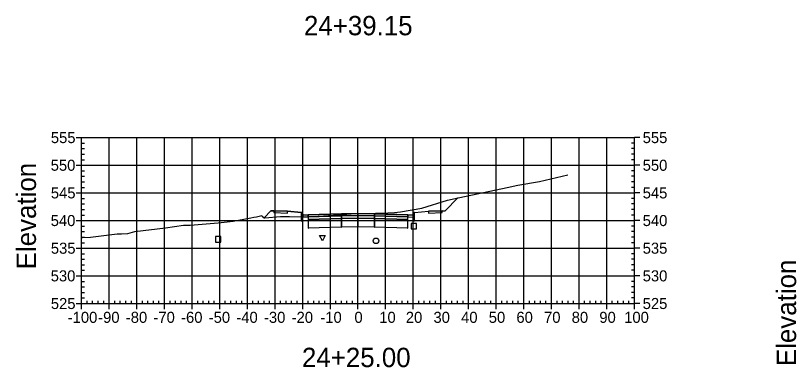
# Model space of a CAD drawing. Extents: x 704834 to 709892, y 372981 to 377533.
# Drawn here: x 707731 to 708013.5, y 376927.7 to 377054.9 of the extents above; entities that cross this region are included whole.
import ezdxf

# ---------------------------------------------------------------- set-up
doc = ezdxf.new("R2010")
doc.units = 0
for name, color, linetype in [('1', 7, 'Continuous'), ('10', 7, 'Continuous'), ('13', 7, 'Continuous'), ('14', 7, 'Continuous'), ('4', 7, 'Continuous'), ('57', 7, 'Continuous'), ('60', 7, 'Continuous'), ('Default_Xsect', 7, 'Continuous'), ('Existing', 7, 'Continuous')]:
    doc.layers.add(name, color=color, linetype=linetype)

msp = doc.modelspace()

# ---------------------------------------------------------------- linework, layer by layer
for points in [[(707886.41, 376984.32), (707891.09, 376988.99)], [(707823.41, 376984.32), (707820.92, 376981.82)], [(707824.41, 376984.36), (707823.41, 376984.32)], [(707885.41, 376984.36), (707886.41, 376984.32)], [(707834.41, 376983.76), (707829.41, 376984.16)], [(707875.41, 376983.76), (707880.41, 376984.16)]]:
    msp.add_lwpolyline(points)
for points in [[(707829.41, 376984.16), (707824.41, 376984.36), (707824.41, 376983.69), (707829.41, 376983.49)], [(707880.41, 376983.49), (707885.41, 376983.69), (707885.41, 376984.36), (707880.41, 376984.16)], [(707834.91, 376982.76), (707834.83, 376983.76), (707834.41, 376983.76), (707834.41, 376980.76), (707834.91, 376980.76)], [(707836.91, 376982.84), (707834.91, 376982.76), (707834.91, 376982.09), (707836.91, 376982.17)], [(707848.91, 376983.2), (707836.91, 376982.84), (707836.91, 376982.17), (707848.91, 376982.53)], [(707848.91, 376982.53), (707836.91, 376982.17), (707836.91, 376981.17), (707848.91, 376981.53)], [(707848.91, 376981.53), (707836.91, 376981.17), (707836.91, 376978.17), (707848.91, 376978.53)], [(707848.86, 376982.48), (707848.96, 376982.48), (707848.96, 376982.58), (707848.86, 376982.58)], [(707848.86, 376981.48), (707848.96, 376981.48), (707848.96, 376981.58), (707848.86, 376981.58)], [(707854.91, 376983.32), (707848.91, 376983.2), (707848.91, 376982.53), (707854.91, 376982.65)], [(707854.91, 376982.65), (707848.91, 376982.53), (707848.91, 376981.53), (707854.91, 376981.65)], [(707854.91, 376981.65), (707848.91, 376981.53), (707848.91, 376978.53), (707854.91, 376978.65)], [(707854.86, 376982.6), (707854.96, 376982.6), (707854.96, 376982.7), (707854.86, 376982.7)], [(707854.86, 376981.6), (707854.96, 376981.6), (707854.96, 376981.7), (707854.86, 376981.7)], [(707854.91, 376982.65), (707860.91, 376982.53), (707860.91, 376983.2), (707854.91, 376983.32)], [(707854.91, 376981.65), (707860.91, 376981.53), (707860.91, 376982.53), (707854.91, 376982.65)], [(707854.91, 376978.65), (707860.91, 376978.53), (707860.91, 376981.53), (707854.91, 376981.65)], [(707860.86, 376982.48), (707860.96, 376982.48), (707860.96, 376982.58), (707860.86, 376982.58)], [(707860.86, 376981.48), (707860.96, 376981.48), (707860.96, 376981.58), (707860.86, 376981.58)], [(707860.91, 376982.53), (707872.91, 376982.17), (707872.91, 376982.84), (707860.91, 376983.2)], [(707860.91, 376981.53), (707872.91, 376981.17), (707872.91, 376982.17), (707860.91, 376982.53)], [(707860.91, 376978.53), (707872.91, 376978.17), (707872.91, 376981.17), (707860.91, 376981.53)], [(707872.91, 376982.17), (707874.91, 376982.09), (707874.91, 376982.76), (707872.91, 376982.84)], [(707874.91, 376980.76), (707875.41, 376980.76), (707875.41, 376983.76), (707875, 376983.76), (707874.91, 376982.76)], [(707836.86, 376981.12), (707836.96, 376981.12), (707836.96, 376981.22), (707836.86, 376981.22)], [(707854.86, 376978.6), (707854.96, 376978.6), (707854.96, 376978.7), (707854.86, 376978.7)], [(707872.86, 376981.12), (707872.96, 376981.12), (707872.96, 376981.22), (707872.86, 376981.22)], [(707836.86, 376978.12), (707836.96, 376978.12), (707836.96, 376978.22), (707836.86, 376978.22)], [(707848.86, 376978.48), (707848.96, 376978.48), (707848.96, 376978.58), (707848.86, 376978.58)], [(707860.86, 376978.48), (707860.96, 376978.48), (707860.96, 376978.58), (707860.86, 376978.58)], [(707872.86, 376978.12), (707872.96, 376978.12), (707872.96, 376978.22), (707872.86, 376978.22)]]:
    msp.add_lwpolyline(points, close=True)
at = {"layer": '1'}
msp.add_lwpolyline([(707842.01, 376973.47), (707841.01, 376975.47), (707843.01, 376975.47)], close=True, dxfattribs=at)
at = {"layer": '10'}
msp.add_lwpolyline([(707803.33, 376973.05), (707805.33, 376973.05), (707805.33, 376975.05), (707803.33, 376975.05)], close=True, dxfattribs=at)
at = {"layer": '13'}
msp.add_circle((707861.43, 376973.48), 1, dxfattribs=at)
at = {"layer": '14'}
for points in [[(707891.09, 376988.99), (707891.09, 376989.04), (707891.09, 376988.99), (707891.04, 376988.99), (707891.09, 376988.99), (707891.09, 376988.94), (707891.09, 376988.99), (707891.14, 376988.99)], [(707820.92, 376981.82), (707820.92, 376981.87), (707820.92, 376981.82), (707820.87, 376981.82), (707820.92, 376981.82), (707820.92, 376981.77), (707820.92, 376981.82), (707820.97, 376981.82)], [(707836.91, 376982.84), (707836.91, 376982.89), (707836.91, 376982.84), (707836.86, 376982.84), (707836.91, 376982.84), (707836.91, 376982.79), (707836.91, 376982.84), (707836.96, 376982.84)], [(707854.91, 376983.32), (707854.91, 376983.37), (707854.91, 376983.32), (707854.86, 376983.32), (707854.91, 376983.32), (707854.91, 376983.27), (707854.91, 376983.32), (707854.96, 376983.32)], [(707872.91, 376982.84), (707872.91, 376982.89), (707872.91, 376982.84), (707872.86, 376982.84), (707872.91, 376982.84), (707872.91, 376982.79), (707872.91, 376982.84), (707872.96, 376982.84)]]:
    msp.add_lwpolyline(points, dxfattribs=at)
at = {"layer": '4'}
msp.add_lwpolyline([(707874.12, 376977.8), (707876.12, 376977.8), (707876.12, 376979.8), (707874.12, 376979.8)], close=True, dxfattribs=at)
at = {"layer": '57'}
for p, q in [((707752.91, 377010.82), (707754.91, 377010.82)), ((707754.91, 377010.82), (707954.91, 377010.82)), ((707754.91, 376950.82), (707754.91, 377010.82)), ((707754.91, 376950.82), (707754.91, 377010.82)), ((707764.91, 376950.82), (707764.91, 377010.82)), ((707774.91, 376950.82), (707774.91, 377010.82)), ((707784.91, 376950.82), (707784.91, 377010.82)), ((707794.91, 376950.82), (707794.91, 377010.82)), ((707804.91, 376950.82), (707804.91, 377010.82)), ((707814.91, 376950.82), (707814.91, 377010.82)), ((707824.91, 376950.82), (707824.91, 377010.82)), ((707834.91, 376950.82), (707834.91, 377010.82)), ((707844.91, 376950.82), (707844.91, 377010.82)), ((707854.91, 376950.82), (707854.91, 377010.82)), ((707864.91, 376950.82), (707864.91, 377010.82)), ((707874.91, 376950.82), (707874.91, 377010.82)), ((707884.91, 376950.82), (707884.91, 377010.82)), ((707894.91, 376950.82), (707894.91, 377010.82)), ((707904.91, 376950.82), (707904.91, 377010.82)), ((707914.91, 376950.82), (707914.91, 377010.82)), ((707924.91, 376950.82), (707924.91, 377010.82)), ((707934.91, 376950.82), (707934.91, 377010.82)), ((707944.91, 376950.82), (707944.91, 377010.82)), ((707954.91, 376950.82), (707954.91, 377010.82)), ((707954.91, 376950.82), (707954.91, 377010.82)), ((707956.91, 377010.82), (707954.91, 377010.82)), ((707754.91, 377008.82), (707755.91, 377008.82)), ((707954.91, 377008.82), (707953.91, 377008.82)), ((707754.91, 377006.82), (707755.91, 377006.82)), ((707754.91, 377004.82), (707755.91, 377004.82)), ((707954.91, 377006.82), (707953.91, 377006.82)), ((707954.91, 377004.82), (707953.91, 377004.82)), ((707754.91, 377002.82), (707755.91, 377002.82)), ((707954.91, 377002.82), (707953.91, 377002.82)), ((707752.91, 377000.82), (707754.91, 377000.82)), ((707754.91, 377000.82), (707954.91, 377000.82)), ((707754.91, 376998.82), (707755.91, 376998.82)), ((707954.91, 376998.82), (707953.91, 376998.82)), ((707956.91, 377000.82), (707954.91, 377000.82)), ((707754.91, 376996.82), (707755.91, 376996.82)), ((707954.91, 376996.82), (707953.91, 376996.82)), ((707754.91, 376994.82), (707755.91, 376994.82)), ((707754.91, 376992.82), (707755.91, 376992.82)), ((707954.91, 376994.82), (707953.91, 376994.82)), ((707954.91, 376992.82), (707953.91, 376992.82)), ((707752.91, 376990.82), (707754.91, 376990.82)), ((707754.91, 376990.82), (707954.91, 376990.82)), ((707956.91, 376990.82), (707954.91, 376990.82)), ((707754.91, 376988.82), (707755.91, 376988.82)), ((707954.91, 376988.82), (707953.91, 376988.82)), ((707754.91, 376986.82), (707755.91, 376986.82)), ((707754.91, 376984.82), (707755.91, 376984.82)), ((707954.91, 376986.82), (707953.91, 376986.82)), ((707954.91, 376984.82), (707953.91, 376984.82)), ((707754.91, 376982.82), (707755.91, 376982.82)), ((707954.91, 376982.82), (707953.91, 376982.82)), ((707752.91, 376980.82), (707754.91, 376980.82)), ((707754.91, 376980.82), (707954.91, 376980.82)), ((707754.91, 376978.82), (707755.91, 376978.82)), ((707954.91, 376978.82), (707953.91, 376978.82)), ((707956.91, 376980.82), (707954.91, 376980.82)), ((707754.91, 376976.82), (707755.91, 376976.82)), ((707954.91, 376976.82), (707953.91, 376976.82)), ((707754.91, 376974.82), (707755.91, 376974.82)), ((707954.91, 376974.82), (707953.91, 376974.82)), ((707752.91, 376970.82), (707754.91, 376970.82)), ((707754.91, 376972.82), (707755.91, 376972.82)), ((707754.91, 376970.82), (707954.91, 376970.82)), ((707954.91, 376972.82), (707953.91, 376972.82)), ((707956.91, 376970.82), (707954.91, 376970.82)), ((707754.91, 376968.82), (707755.91, 376968.82)), ((707954.91, 376968.82), (707953.91, 376968.82)), ((707754.91, 376966.82), (707755.91, 376966.82)), ((707754.91, 376964.82), (707755.91, 376964.82)), ((707954.91, 376966.82), (707953.91, 376966.82)), ((707954.91, 376964.82), (707953.91, 376964.82)), ((707754.91, 376962.82), (707755.91, 376962.82)), ((707954.91, 376962.82), (707953.91, 376962.82)), ((707752.91, 376960.82), (707754.91, 376960.82)), ((707754.91, 376960.82), (707954.91, 376960.82)), ((707956.91, 376960.82), (707954.91, 376960.82)), ((707754.91, 376958.82), (707755.91, 376958.82)), ((707754.91, 376956.82), (707755.91, 376956.82)), ((707954.91, 376958.82), (707953.91, 376958.82)), ((707954.91, 376956.82), (707953.91, 376956.82)), ((707754.91, 376954.82), (707755.91, 376954.82)), ((707954.91, 376954.82), (707953.91, 376954.82)), ((707752.91, 376950.82), (707754.91, 376950.82)), ((707754.91, 376952.82), (707755.91, 376952.82)), ((707754.91, 376950.82), (707954.91, 376950.82)), ((707754.91, 376950.82), (707954.91, 376950.82)), ((707754.91, 376948.82), (707754.91, 376950.82)), ((707756.91, 376950.82), (707756.91, 376951.82)), ((707758.91, 376950.82), (707758.91, 376951.82)), ((707760.91, 376950.82), (707760.91, 376951.82)), ((707762.91, 376950.82), (707762.91, 376951.82)), ((707764.91, 376948.82), (707764.91, 376950.82)), ((707766.91, 376950.82), (707766.91, 376951.82)), ((707768.91, 376950.82), (707768.91, 376951.82)), ((707770.91, 376950.82), (707770.91, 376951.82)), ((707772.91, 376950.82), (707772.91, 376951.82)), ((707774.91, 376948.82), (707774.91, 376950.82)), ((707776.91, 376950.82), (707776.91, 376951.82)), ((707778.91, 376950.82), (707778.91, 376951.82)), ((707780.91, 376950.82), (707780.91, 376951.82)), ((707782.91, 376950.82), (707782.91, 376951.82)), ((707784.91, 376948.82), (707784.91, 376950.82)), ((707786.91, 376950.82), (707786.91, 376951.82)), ((707788.91, 376950.82), (707788.91, 376951.82)), ((707790.91, 376950.82), (707790.91, 376951.82)), ((707792.91, 376950.82), (707792.91, 376951.82)), ((707794.91, 376948.82), (707794.91, 376950.82)), ((707796.91, 376950.82), (707796.91, 376951.82)), ((707798.91, 376950.82), (707798.91, 376951.82)), ((707800.91, 376950.82), (707800.91, 376951.82)), ((707802.91, 376950.82), (707802.91, 376951.82)), ((707804.91, 376948.82), (707804.91, 376950.82)), ((707806.91, 376950.82), (707806.91, 376951.82)), ((707808.91, 376950.82), (707808.91, 376951.82)), ((707810.91, 376950.82), (707810.91, 376951.82)), ((707812.91, 376950.82), (707812.91, 376951.82)), ((707814.91, 376948.82), (707814.91, 376950.82)), ((707816.91, 376950.82), (707816.91, 376951.82)), ((707818.91, 376950.82), (707818.91, 376951.82)), ((707820.91, 376950.82), (707820.91, 376951.82)), ((707822.91, 376950.82), (707822.91, 376951.82)), ((707824.91, 376948.82), (707824.91, 376950.82)), ((707826.91, 376950.82), (707826.91, 376951.82)), ((707828.91, 376950.82), (707828.91, 376951.82)), ((707830.91, 376950.82), (707830.91, 376951.82)), ((707832.91, 376950.82), (707832.91, 376951.82)), ((707834.91, 376948.82), (707834.91, 376950.82)), ((707836.91, 376950.82), (707836.91, 376951.82)), ((707838.91, 376950.82), (707838.91, 376951.82)), ((707840.91, 376950.82), (707840.91, 376951.82)), ((707842.91, 376950.82), (707842.91, 376951.82)), ((707844.91, 376948.82), (707844.91, 376950.82)), ((707846.91, 376950.82), (707846.91, 376951.82)), ((707848.91, 376950.82), (707848.91, 376951.82)), ((707850.91, 376950.82), (707850.91, 376951.82)), ((707852.91, 376950.82), (707852.91, 376951.82)), ((707854.91, 376948.82), (707854.91, 376950.82)), ((707856.91, 376950.82), (707856.91, 376951.82)), ((707858.91, 376950.82), (707858.91, 376951.82)), ((707860.91, 376950.82), (707860.91, 376951.82)), ((707862.91, 376950.82), (707862.91, 376951.82)), ((707864.91, 376948.82), (707864.91, 376950.82)), ((707866.91, 376950.82), (707866.91, 376951.82)), ((707868.91, 376950.82), (707868.91, 376951.82)), ((707870.91, 376950.82), (707870.91, 376951.82)), ((707872.91, 376950.82), (707872.91, 376951.82)), ((707874.91, 376948.82), (707874.91, 376950.82)), ((707876.91, 376950.82), (707876.91, 376951.82)), ((707878.91, 376950.82), (707878.91, 376951.82)), ((707880.91, 376950.82), (707880.91, 376951.82)), ((707882.91, 376950.82), (707882.91, 376951.82)), ((707884.91, 376948.82), (707884.91, 376950.82)), ((707886.91, 376950.82), (707886.91, 376951.82)), ((707888.91, 376950.82), (707888.91, 376951.82)), ((707890.91, 376950.82), (707890.91, 376951.82)), ((707892.91, 376950.82), (707892.91, 376951.82)), ((707894.91, 376948.82), (707894.91, 376950.82)), ((707896.91, 376950.82), (707896.91, 376951.82)), ((707898.91, 376950.82), (707898.91, 376951.82)), ((707900.91, 376950.82), (707900.91, 376951.82)), ((707902.91, 376950.82), (707902.91, 376951.82)), ((707904.91, 376948.82), (707904.91, 376950.82)), ((707906.91, 376950.82), (707906.91, 376951.82)), ((707908.91, 376950.82), (707908.91, 376951.82)), ((707910.91, 376950.82), (707910.91, 376951.82)), ((707912.91, 376950.82), (707912.91, 376951.82)), ((707914.91, 376948.82), (707914.91, 376950.82)), ((707916.91, 376950.82), (707916.91, 376951.82)), ((707918.91, 376950.82), (707918.91, 376951.82)), ((707920.91, 376950.82), (707920.91, 376951.82)), ((707922.91, 376950.82), (707922.91, 376951.82)), ((707924.91, 376948.82), (707924.91, 376950.82)), ((707926.91, 376950.82), (707926.91, 376951.82)), ((707928.91, 376950.82), (707928.91, 376951.82)), ((707930.91, 376950.82), (707930.91, 376951.82)), ((707932.91, 376950.82), (707932.91, 376951.82)), ((707934.91, 376948.82), (707934.91, 376950.82)), ((707936.91, 376950.82), (707936.91, 376951.82)), ((707938.91, 376950.82), (707938.91, 376951.82)), ((707940.91, 376950.82), (707940.91, 376951.82)), ((707942.91, 376950.82), (707942.91, 376951.82)), ((707944.91, 376948.82), (707944.91, 376950.82)), ((707946.91, 376950.82), (707946.91, 376951.82)), ((707948.91, 376950.82), (707948.91, 376951.82)), ((707950.91, 376950.82), (707950.91, 376951.82)), ((707952.91, 376950.82), (707952.91, 376951.82)), ((707954.91, 376952.82), (707953.91, 376952.82)), ((707954.91, 376948.82), (707954.91, 376950.82)), ((707956.91, 376950.82), (707954.91, 376950.82))]:
    msp.add_line(p, q, dxfattribs=at)
at = {"layer": 'Default_Xsect'}
msp.add_lwpolyline([(707820.92, 376981.82), (707823.41, 376984.32), (707824.41, 376984.36), (707829.41, 376984.16), (707834.41, 376983.76), (707834.83, 376983.76), (707834.91, 376982.76), (707836.91, 376982.84), (707848.91, 376983.2), (707854.91, 376983.32), (707860.91, 376983.2), (707872.91, 376982.84), (707874.91, 376982.76), (707875, 376983.76), (707875.41, 376983.76), (707880.41, 376984.16), (707885.41, 376984.36), (707886.41, 376984.32), (707891.09, 376988.99)], dxfattribs=at)
at = {"layer": 'Existing'}
msp.add_lwpolyline([(707754.91, 376974.64), (707755.2, 376974.66), (707758.13, 376974.81), (707767.73, 376975.99), (707769.38, 376976.05), (707771.7, 376976.13), (707774.22, 376976.91), (707785.23, 376978.13), (707791.78, 376979.19), (707794.25, 376979.2), (707804.34, 376980.05), (707809.71, 376980.64), (707816.14, 376981.79), (707817.24, 376982.04), (707818.21, 376982.11), (707820.09, 376982.62), (707820.26, 376982.46), (707820.95, 376981.79), (707821.15, 376981.82), (707826.93, 376982.33), (707828.46, 376982.34), (707830.08, 376982.23), (707836.84, 376982.13), (707846.1, 376982.73), (707852.44, 376983.21), (707865.69, 376983.6), (707868.17, 376983.72), (707870.3, 376983.92), (707877.97, 376985.33), (707887.31, 376988.25), (707887.84, 376988.35), (707889.45, 376988.64), (707908.87, 376992.81), (707912.73, 376993.63), (707920.62, 376994.97), (707930.86, 376997.3)], dxfattribs=at)

# ---------------------------------------------------------------- texts
at = {"layer": '1'}
for s, p in [('24+39.15', (707835.36, 377047.82)), ('24+25.00', (707834.64, 376927.82))]:
    msp.add_text(s, height=7, dxfattribs=at).set_placement(p)
at = {"layer": '14'}
for p in [(707824.38, 376984.31), (707885.38, 376984.31), (707824.38, 376983.64), (707829.38, 376983.44), (707880.38, 376983.44), (707885.38, 376983.64)]:
    msp.add_text('+', height=0.1, dxfattribs=at).set_placement(p)
at = {"layer": '57'}
for s, p in [('555', (707743.79, 377008.82)), ('555', (707957.91, 377008.82)), ('550', (707743.74, 376998.82)), ('550', (707957.91, 376998.82)), ('545', (707743.79, 376988.82)), ('545', (707957.91, 376988.82)), ('540', (707743.74, 376978.82)), ('540', (707957.91, 376978.82)), ('535', (707743.79, 376968.82)), ('535', (707957.91, 376968.82)), ('530', (707743.74, 376958.82)), ('530', (707957.91, 376958.82)), ('525', (707743.79, 376948.82)), ('525', (707957.91, 376948.82)), ('-100', (707749.9, 376943.82)), ('-90', (707760.91, 376943.82)), ('-80', (707770.91, 376943.82)), ('-70', (707780.91, 376943.82)), ('-60', (707790.91, 376943.82)), ('-50', (707800.91, 376943.82)), ('-40', (707810.91, 376943.82)), ('-30', (707820.91, 376943.82)), ('-20', (707830.91, 376943.82)), ('-10', (707841.3, 376943.82)), ('0', (707853.62, 376943.82)), ('10', (707862.61, 376943.82)), ('20', (707872.22, 376943.82)), ('30', (707882.22, 376943.82)), ('40', (707892.22, 376943.82)), ('50', (707902.22, 376943.82)), ('60', (707912.22, 376943.82)), ('70', (707922.22, 376943.82)), ('80', (707932.22, 376943.82)), ('90', (707942.22, 376943.82)), ('100', (707951.21, 376943.82))]:
    msp.add_text(s, height=4, dxfattribs=at).set_placement(p)
at = {"layer": '60'}
for p in [(707738.41, 376963.18), (708013.41, 376928.18)]:
    msp.add_text('Elevation', height=7, rotation=90, dxfattribs=at).set_placement(p)

doc.saveas('drawing.dxf')
